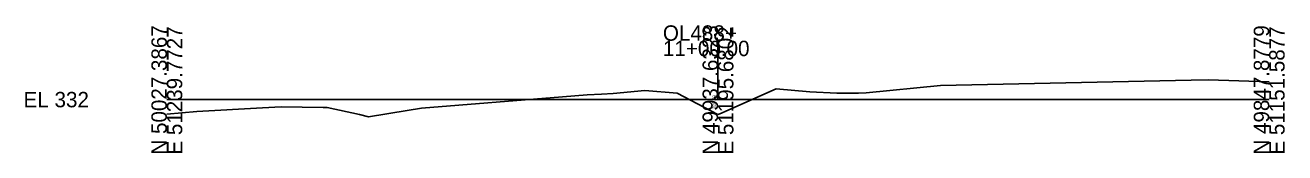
# Model space of a CAD drawing. Extents: x 6002 to 6231, y 90221 to 94244.
# Drawn here: x 6002 to 6230.5, y 91221.3 to 91244.5 of the extents above; entities that cross this region are included whole.
import ezdxf

# ---------------------------------------------------------------- set-up
doc = ezdxf.new("R2010")
doc.units = 0
for name, color, linetype in [('Level 10', 7, 'Continuous'), ('Level 60', 7, 'Continuous'), ('Level 63', 7, 'Continuous')]:
    doc.layers.add(name, color=color, linetype=linetype)

msp = doc.modelspace()

# ---------------------------------------------------------------- linework, layer by layer
at = {"layer": 'Level 60'}
for p, q in [((6154.58, 91232.2), (6168.05, 91233.56)), ((6168.05, 91233.56), (6213.54, 91234.48)), ((6213.54, 91234.48), (6216.69, 91234.54)), ((6216.69, 91234.54), (6227.67, 91234.18)), ((6073.89, 91229.4), (6099.46, 91231.45)), ((6099.46, 91231.45), (6103.95, 91231.86)), ((6103.95, 91231.86), (6106.54, 91231.97)), ((6106.54, 91231.97), (6108.63, 91232.11)), ((6108.63, 91232.11), (6114.4, 91232.63)), ((6114.4, 91232.63), (6120.27, 91232.17)), ((6120.27, 91232.17), (6127.67, 91228.26)), ((6128.02, 91228.41), (6138.24, 91232.92)), ((6138.24, 91232.92), (6144.36, 91232.41)), ((6144.36, 91232.41), (6149.23, 91232.14)), ((6149.23, 91232.14), (6153.15, 91232.17)), ((6153.15, 91232.17), (6154.58, 91232.2)), ((6027.67, 91228.29), (6033.14, 91228.79)), ((6033.14, 91228.79), (6045.05, 91229.48)), ((6045.05, 91229.48), (6048.41, 91229.67)), ((6048.41, 91229.67), (6056.03, 91229.56)), ((6056.03, 91229.56), (6056.79, 91229.54)), ((6056.79, 91229.54), (6062.63, 91228.23)), ((6064.25, 91227.86), (6071.3, 91229.01)), ((6071.3, 91229.01), (6073.89, 91229.4)), ((6062.63, 91228.23), (6064.25, 91227.86)), ((6127.67, 91228.26), (6128.02, 91228.41))]:
    msp.add_line(p, q, dxfattribs=at)
at = {"layer": 'Level 63'}
for p, q in [((6127.67, 91230.97), (6127.67, 91241.68)), ((6027.67, 91230.97), (6127.67, 91230.97)), ((6127.67, 91230.97), (6227.67, 91230.97))]:
    msp.add_line(p, q, dxfattribs=at)

# ---------------------------------------------------------------- texts
at = {"layer": 'Level 10'}
msp.add_text('329.29', height=0.6, rotation=90, dxfattribs=at).set_placement((6127.27, 91229.26))
at = {"layer": 'Level 63'}
for s, p in [('N 50027.3867', (6027.67, 91220.97)), ('E 51239.7727', (6030.47, 91220.97)), ('N 49937.6323', (6127.67, 91220.97)), ('E 51195.6802', (6130.47, 91220.97)), ('N 49847.8779', (6227.67, 91220.97)), ('E 51151.5877', (6230.47, 91220.97))]:
    msp.add_text(s, height=2.8, rotation=90, dxfattribs=at).set_placement(p)
for s, p in [('OL488+', (6117.67, 91241.68)), ('11+00.00', (6117.67, 91238.88)), ('EL 332', (6001.67, 91229.57))]:
    msp.add_text(s, height=2.8, dxfattribs=at).set_placement(p)

doc.saveas('drawing.dxf')
